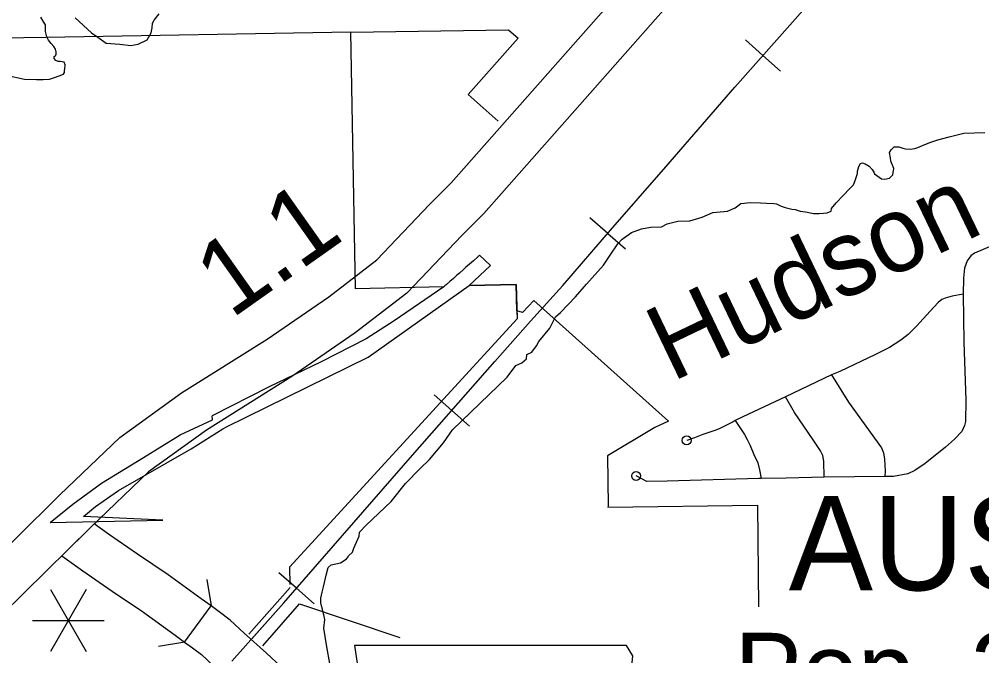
# Model space of a CAD drawing. Extents: x 1367863 to 1368197, y 380048 to 380261.
# Drawn here: x 1367970.56 to 1367991.45, y 380131.45 to 380145.26 of the extents above; entities that cross this region are included whole.
import ezdxf

# ---------------------------------------------------------------- set-up
doc = ezdxf.new("R2010")
doc.units = 0
for name, color, linetype in [('Level 10', 7, 'Continuous'), ('Level 21', 7, 'Continuous'), ('Level 33', 7, 'Continuous'), ('Level 35', 7, 'Continuous'), ('Level 37', 7, 'Continuous'), ('Level 40', 7, 'Continuous'), ('Level 48', 7, 'Continuous'), ('Level 6', 7, 'Continuous')]:
    doc.layers.add(name, color=color, linetype=linetype)

msp = doc.modelspace()

# ---------------------------------------------------------------- linework, layer by layer
at = {"layer": 'Level 10'}
for points in [[(1367979.459, 380141.243), (1367979.499, 380141.278), (1367979.93, 380141.711), (1367986.716, 380149.398)], [(1367987.489, 380148.808), (1367980.638, 380141.048), (1367980.164, 380140.57)], [(1367971.441, 380134.938), (1367972.74, 380136.189), (1367974.081, 380137.153), (1367975.94, 380138.32), (1367977.279, 380139.239), (1367978.321, 380140.043), (1367979.462, 380141.24)], [(1367980.164, 380140.57), (1367978.972, 380139.32), (1367977.85, 380138.454), (1367976.472, 380137.509), (1367974.622, 380136.347), (1367973.363, 380135.442), (1367972.114, 380134.239)], [(1367969.491, 380133.018), (1367971.441, 380134.938)], [(1367972.114, 380134.239), (1367970.172, 380132.327)], [(1367972.187, 380134.31), (1367972.114, 380134.239), (1367971.485, 380133.62), (1367971.937, 380133.293), (1367972.575, 380132.851), (1367973.233, 380132.406), (1367973.94, 380131.897), (1367974.147, 380131.746), (1367974.719, 380132.53)], [(1367974.719, 380132.53), (1367974.509, 380132.683), (1367973.788, 380133.202), (1367973.123, 380133.652), (1367972.498, 380134.085), (1367972.187, 380134.31)], [(1367976.324, 380131.118), (1367976.233, 380131.216), (1367975.922, 380131.507), (1367975.438, 380131.938), (1367975.133, 380132.224), (1367974.894, 380132.402), (1367974.719, 380132.53)], [(1367974.147, 380131.746), (1367974.318, 380131.621), (1367974.51, 380131.478), (1367974.783, 380131.222), (1367975.267, 380130.791), (1367975.546, 380130.53), (1367975.614, 380130.457)]]:
    msp.add_lwpolyline(points, dxfattribs=at)
at = {"layer": 'Level 21'}
msp.add_lwpolyline([(1367977.833, 380131.673), (1367978.129, 380129.704), (1367977.998, 380126.716), (1367978.26, 380126.552), (1367978.753, 380126.552), (1367978.753, 380125.501), (1367982.889, 380125.501), (1367983.086, 380125.928), (1367983.02, 380126.618), (1367983.119, 380127.405), (1367983.48, 380128.029), (1367983.71, 380128.489), (1367984.038, 380128.981), (1367984.235, 380129.507), (1367984.399, 380129.933), (1367984.695, 380130.294), (1367984.76, 380130.524), (1367984.629, 380130.688), (1367983.611, 380130.688), (1367983.841, 380131.148), (1367983.874, 380131.444), (1367983.738, 380131.67)], close=True, dxfattribs=at)
at = {"layer": 'Level 33'}
for points in [[(1367993.372, 380140.951), (1367991.99, 380140.48), (1367991.286, 380140.188), (1367991.207, 380140.128), (1367991.129, 380140.017), (1367991.068, 380139.864), (1367991.05, 380139.641), (1367991.045, 380139.294)], [(1367991.045, 380139.294), (1367990.805, 380139.255), (1367990.651, 380139.212), (1367990.579, 380139.183), (1367990.498, 380139.116), (1367990.325, 380138.929), (1367990.028, 380138.603), (1367989.85, 380138.421), (1367989.687, 380138.296), (1367989.443, 380138.142), (1367989.136, 380137.989), (1367988.369, 380137.62), (1367988.186, 380137.548)], [(1367991.045, 380139.294), (1367991.059, 380138.258), (1367991.102, 380136.996), (1367991.092, 380136.535), (1367991.068, 380136.449), (1367991.016, 380136.315), (1367990.857, 380136.147), (1367990.656, 380135.979)], [(1367988.186, 380137.548), (1367987.184, 380137.069)], [(1367988.186, 380137.548), (1367988.556, 380136.954), (1367989.27, 380135.961), (1367989.313, 380135.851), (1367989.332, 380135.716), (1367989.347, 380135.452), (1367989.342, 380135.337)], [(1367987.184, 380137.069), (1367986.262, 380136.632), (1367986.097, 380136.552)], [(1367988.024, 380135.326), (1367988.019, 380135.673), (1367987.995, 380135.798), (1367987.947, 380135.898), (1367987.788, 380136.134), (1367987.381, 380136.728), (1367987.184, 380137.069)], [(1367986.097, 380136.552), (1367986.049, 380136.529), (1367985.749, 380136.372), (1367985.655, 380136.34), (1367985.394, 380136.251), (1367985.211, 380136.178), (1367985.043, 380136.124)], [(1367986.097, 380136.552), (1367986.299, 380136.248), (1367986.356, 380136.141), (1367986.421, 380136.009), (1367986.502, 380135.817), (1367986.586, 380135.636), (1367986.62, 380135.486), (1367986.659, 380135.295)], [(1367990.656, 380135.979), (1367990.22, 380135.62), (1367989.994, 380135.467), (1367989.841, 380135.4), (1367989.529, 380135.337), (1367989.342, 380135.337)], [(1367986.659, 380135.295), (1367986.605, 380135.294), (1367984.618, 380135.24), (1367984.175, 380135.229), (1367983.945, 380135.352)], [(1367987.198, 380135.306), (1367986.659, 380135.295)], [(1367988.024, 380135.326), (1367987.198, 380135.306)], [(1367989.342, 380135.337), (1367988.024, 380135.325)]]:
    msp.add_lwpolyline(points, dxfattribs=at)
for centre in [(1367985.043, 380136.124), (1367983.945, 380135.352)]:
    msp.add_circle(centre, 0.097, dxfattribs=at)
at = {"layer": 'Level 35'}
for points in [[(1367970.272, 380144.05), (1367970.672, 380143.966), (1367970.93, 380143.959), (1367971.079, 380143.953), (1367971.214, 380143.966), (1367971.324, 380143.998), (1367971.421, 380144.037), (1367971.518, 380144.069), (1367971.537, 380144.108), (1367971.537, 380144.153), (1367971.55, 380144.185), (1367971.556, 380144.275), (1367971.53, 380144.334), (1367971.447, 380144.346), (1367971.401, 380144.346), (1367971.35, 380144.366), (1367971.318, 380144.411), (1367971.318, 380144.456), (1367971.343, 380144.469), (1367971.356, 380144.508), (1367971.356, 380144.553), (1367971.343, 380144.611), (1367971.305, 380144.669), (1367971.247, 380144.74), (1367971.195, 380144.811), (1367971.156, 380144.882), (1367971.124, 380144.998), (1367971.124, 380145.069), (1367971.124, 380145.14), (1367971.079, 380145.224), (1367971.027, 380145.308)], [(1367971.769, 380145.295), (1367972.124, 380144.972), (1367972.266, 380144.876), (1367972.446, 380144.747), (1367972.737, 380144.721), (1367972.982, 380144.695), (1367973.137, 380144.721), (1367973.33, 380144.818), (1367973.421, 380144.966), (1367973.44, 380145.076), (1367973.446, 380145.179), (1367973.485, 380145.243), (1367973.595, 380145.379)], [(1367981.781, 380138.172), (1367981.836, 380138.269), (1367982.074, 380138.562), (1367982.196, 380138.805), (1367982.305, 380138.901), (1367982.627, 380139.236), (1367982.87, 380139.513), (1367983.234, 380139.923), (1367983.381, 380140.141), (1367983.548, 380140.388), (1367983.645, 380140.493), (1367983.846, 380140.636), (1367984.059, 380140.715), (1367984.26, 380140.753), (1367984.495, 380140.757), (1367984.62, 380140.82), (1367984.847, 380140.879), (1367985.11, 380140.891), (1367985.378, 380140.967), (1367985.609, 380141.067), (1367985.927, 380141.101), (1367986.095, 380141.172), (1367986.22, 380141.264), (1367986.425, 380141.285), (1367986.643, 380141.281), (1367986.777, 380141.272), (1367986.936, 380141.268), (1367986.991, 380141.26), (1367987.091, 380141.21), (1367987.179, 380141.176), (1367987.322, 380141.143), (1367987.393, 380141.134), (1367987.506, 380141.096), (1367987.623, 380141.084), (1367987.791, 380141.046), (1367987.916, 380141.046), (1367988.008, 380141.055), (1367988.088, 380141.059), (1367988.176, 380141.101), (1367988.184, 380141.155), (1367988.289, 380141.277), (1367988.44, 380141.436), (1367988.586, 380141.591), (1367988.662, 380141.67), (1367988.699, 380141.767), (1367988.75, 380141.913), (1367988.75, 380141.968), (1367988.779, 380142.068), (1367988.817, 380142.135), (1367988.854, 380142.148), (1367988.917, 380142.123), (1367989.001, 380142.077), (1367989.064, 380142.001), (1367989.114, 380141.93), (1367989.118, 380141.905), (1367989.273, 380141.8), (1367989.344, 380141.796), (1367989.445, 380141.813), (1367989.512, 380141.888), (1367989.537, 380142.022), (1367989.474, 380142.182), (1367989.466, 380142.257), (1367989.445, 380142.374), (1367989.478, 380142.433), (1367989.541, 380142.496), (1367989.646, 380142.496), (1367989.734, 380142.466), (1367989.792, 380142.454), (1367989.889, 380142.446), (1367989.993, 380142.462), (1367990.06, 380142.483), (1367990.157, 380142.521), (1367990.32, 380142.592), (1367990.492, 380142.647), (1367990.735, 380142.709), (1367991.053, 380142.789), (1367991.509, 380142.806)], [(1367977.308, 380131.239), (1367977.225, 380131.683), (1367977.17, 380132.051), (1367977.191, 380132.236), (1367977.166, 380132.34), (1367977.149, 380132.408), (1367977.141, 380132.462), (1367977.12, 380132.529), (1367977.103, 380132.596), (1367977.103, 380132.651), (1367977.103, 380132.701), (1367977.133, 380132.831), (1367977.162, 380132.948), (1367977.221, 380133.195), (1367977.258, 380133.363), (1367977.329, 380133.421), (1367977.53, 380133.467), (1367977.606, 380133.514), (1367977.66, 380133.555), (1367977.698, 380133.597), (1367977.702, 380133.614), (1367977.79, 380133.694), (1367977.815, 380133.786), (1367977.937, 380134.041), (1367977.945, 380134.129), (1367978.079, 380134.276), (1367978.221, 380134.41), (1367978.632, 380134.8), (1367978.938, 380135.189), (1367979.256, 380135.512), (1367979.461, 380135.705), (1367979.763, 380136.073), (1367979.959, 380136.35), (1367981.145, 380137.498), (1367981.337, 380137.745), (1367981.463, 380137.804), (1367981.563, 380137.896), (1367981.576, 380137.984), (1367981.681, 380138.038), (1367981.781, 380138.172)]]:
    msp.add_lwpolyline(points, dxfattribs=at)
at = {"layer": 'Level 37'}
for points in [[(1367974.625, 380133.104), (1367974.719, 380132.53)], [(1367974.153, 380131.742), (1367973.578, 380131.648)]]:
    msp.add_lwpolyline(points, dxfattribs=at)
at = {"layer": 'Level 40'}
for p, q in [((1367986.698, 380144.477), (1367986.315, 380144.818)), ((1367986.698, 380144.477), (1367987.081, 380144.137)), ((1367983.329, 380140.617), (1367982.941, 380140.952)), ((1367983.329, 380140.617), (1367983.717, 380140.283)), ((1367979.945, 380136.772), (1367979.56, 380137.109)), ((1367979.945, 380136.772), (1367980.33, 380136.434)), ((1367976.574, 380132.914), (1367976.188, 380133.251)), ((1367976.574, 380132.914), (1367976.959, 380132.577))]:
    msp.add_line(p, q, dxfattribs=at)
for points in [[(1367975.603, 380131.816), (1367976.298, 380132.599), (1367979.095, 380135.801), (1367980.876, 380137.834), (1367981.652, 380138.708), (1367982.351, 380139.484), (1367983.389, 380140.687), (1367984.591, 380142.064), (1367986.088, 380143.791), (1367987.399, 380145.266), (1367988.273, 380146.261), (1367989.355, 380147.507), (1367991.846, 380150.349)], [(1367975.172, 380131.331), (1367976.298, 380132.599), (1367979.095, 380135.801), (1367980.876, 380137.834), (1367981.652, 380138.708), (1367982.351, 380139.484), (1367983.389, 380140.687), (1367984.591, 380142.064), (1367986.088, 380143.791), (1367987.399, 380145.266), (1367988.273, 380146.261), (1367989.355, 380147.507)]]:
    msp.add_lwpolyline(points, dxfattribs=at)
at = {"layer": 'Level 48'}
for p, q in [((1367972.01, 380132.887), (1367971.234, 380131.543)), ((1367971.234, 380132.887), (1367972.01, 380131.543)), ((1367970.845, 380132.215), (1367972.398, 380132.215))]:
    msp.add_line(p, q, dxfattribs=at)
at = {"layer": 'Level 6'}
msp.add_line((1367983.335, 380134.706), (1367983.332, 380134.672), dxfattribs=at)
for points in [[(1367977.754, 380144.98), (1367971.136, 380144.869)], [(1367977.754, 380144.98), (1367981.174, 380145.037), (1367981.385, 380144.851), (1367980.303, 380143.632), (1367980.952, 380143.055)], [(1367977.853, 380139.414), (1367977.754, 380144.98)], [(1367977.853, 380139.414), (1367977.754, 380144.98)], [(1367971.136, 380144.869), (1367966.858, 380144.806)], [(1367984.649, 380136.541), (1367981.723, 380139.158), (1367981.482, 380138.902), (1367981.357, 380138.932), (1367981.34, 380139.505), (1367980.322, 380139.484), (1367980.786, 380139.92), (1367980.546, 380140.141), (1367980.507, 380140.106), (1367980.412, 380140.022), (1367980.326, 380139.946), (1367980.252, 380139.881), (1367980.199, 380139.834), (1367980.112, 380139.756), (1367980.05, 380139.702), (1367979.978, 380139.637), (1367979.901, 380139.569), (1367979.83, 380139.507), (1367979.796, 380139.476), (1367979.772, 380139.455)], [(1367971.231, 380134.343), (1367973.676, 380134.395), (1367971.949, 380134.47), (1367972.212, 380134.691), (1367972.715, 380135.032), (1367974.285, 380135.941), (1367974.973, 380136.372), (1367975.054, 380136.415), (1367978.133, 380137.927), (1367980.322, 380139.484), (1367981.34, 380139.505), (1367981.362, 380138.763)], [(1367979.772, 380139.455), (1367978.697, 380138.719), (1367978.087, 380138.329), (1367977.111, 380137.828), (1367975.964, 380137.279), (1367974.746, 380136.658)], [(1367979.772, 380139.455), (1367977.853, 380139.414)], [(1367979.772, 380139.455), (1367977.853, 380139.414)], [(1367981.357, 380138.932), (1367981.362, 380138.763), (1367976.422, 380133.371), (1367976.433, 380132.997)], [(1367974.748, 380136.572), (1367974.746, 380136.658)], [(1367971.231, 380134.343), (1367971.718, 380134.74), (1367972.34, 380135.192), (1367973.255, 380135.753), (1367974.048, 380136.242), (1367974.748, 380136.572)], [(1367984.649, 380136.541), (1367984.353, 380136.402), (1367983.327, 380135.788), (1367983.335, 380134.706)], [(1367983.332, 380134.672), (1367986.577, 380134.714), (1367986.603, 380132.508)], [(1367975.541, 380131.918), (1367976.212, 380132.674), (1367976.435, 380132.929)], [(1367975.843, 380131.664), (1367976.642, 380132.575)], [(1367976.642, 380132.575), (1367978.819, 380131.845)]]:
    msp.add_lwpolyline(points, dxfattribs=at)

# ---------------------------------------------------------------- texts
at = {"layer": 'Level 35'}
msp.add_text('Hudson', height=1.6394, rotation=25.63, dxfattribs=at).set_placement((1367984.718, 380137.38))
at = {"layer": 'Level 48'}
msp.add_text('1.1', height=1.6394, rotation=35.2492, dxfattribs=at).set_placement((1367975.155, 380138.746))
at = {"layer": 'Level 6'}
for s, height, p in [('AUSTIN', 2.0492, (1367987.257, 380132.87)), ('Pop. 2,038', 1.6394, (1367986.08, 380130.307))]:
    msp.add_text(s, height=height, dxfattribs=at).set_placement(p)

doc.saveas('drawing.dxf')
